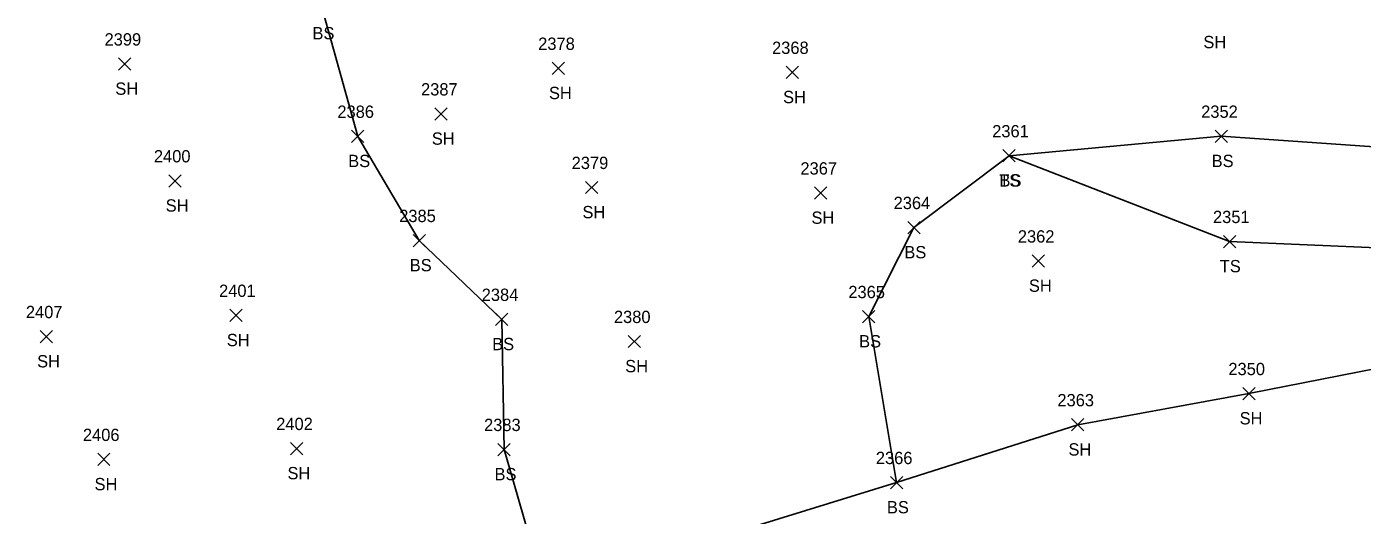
# Model space of a CAD drawing. Extents: x 1443590 to 1445966, y 578314 to 580556.
# Drawn here: x 1444550.7 to 1444767.8, y 578975.6 to 579055 of the extents above; entities that cross this region are included whole.
import ezdxf

# ---------------------------------------------------------------- set-up
doc = ezdxf.new("R2010")
doc.units = 0
for name, color, linetype in [('L_A', 7, 'Continuous'), ('L_I', 7, 'Continuous'), ('L_TIC', 7, 'Continuous'), ('LELB', 7, 'Continuous'), ('LSOGP', 7, 'Continuous')]:
    doc.layers.add(name, color=color, linetype=linetype)

msp = doc.modelspace()

# ---------------------------------------------------------------- linework, layer by layer
at = {"layer": 'L_TIC'}
for points in [[(1444565.63, 579047.93), (1444567.63, 579049.93)], [(1444567.63, 579047.93), (1444565.63, 579049.93)], [(1444636.1, 579047.23), (1444638.1, 579049.23)], [(1444638.1, 579047.23), (1444636.1, 579049.23)], [(1444674.16, 579046.57), (1444676.16, 579048.57)], [(1444676.16, 579046.57), (1444674.16, 579048.57)], [(1444617.06, 579039.82), (1444619.06, 579041.82)], [(1444619.06, 579039.82), (1444617.06, 579041.82)], [(1444603.52, 579036.18), (1444605.52, 579038.18)], [(1444605.52, 579036.18), (1444603.52, 579038.18)], [(1444743.86, 579036.19), (1444745.86, 579038.19)], [(1444745.86, 579036.19), (1444743.86, 579038.19)], [(1444709.37, 579033.02), (1444711.37, 579035.02)], [(1444711.37, 579033.02), (1444709.37, 579035.02)], [(1444709.37, 579033.02), (1444711.37, 579035.02)], [(1444711.37, 579033.02), (1444709.37, 579035.02)], [(1444573.8, 579028.95), (1444575.8, 579030.95)], [(1444575.8, 579028.95), (1444573.8, 579030.95)], [(1444641.55, 579027.87), (1444643.55, 579029.87)], [(1444643.55, 579027.87), (1444641.55, 579029.87)], [(1444678.77, 579026.97), (1444680.77, 579028.97)], [(1444680.77, 579026.97), (1444678.77, 579028.97)], [(1444693.91, 579021.36), (1444695.91, 579023.36)], [(1444695.91, 579021.36), (1444693.91, 579023.36)], [(1444613.51, 579019.25), (1444615.51, 579021.25)], [(1444615.51, 579019.25), (1444613.51, 579021.25)], [(1444745.21, 579019.09), (1444747.21, 579021.09)], [(1444747.21, 579019.09), (1444745.21, 579021.09)], [(1444714.11, 579015.92), (1444716.11, 579017.92)], [(1444716.11, 579015.92), (1444714.11, 579017.92)], [(1444583.74, 579007.09), (1444585.74, 579009.09)], [(1444585.74, 579007.09), (1444583.74, 579009.09)], [(1444626.92, 579006.44), (1444628.92, 579008.44)], [(1444628.92, 579006.44), (1444626.92, 579008.44)], [(1444686.56, 579006.89), (1444688.56, 579008.89)], [(1444688.56, 579006.89), (1444686.56, 579008.89)], [(1444552.91, 579003.64), (1444554.91, 579005.64)], [(1444554.91, 579003.64), (1444552.91, 579005.64)], [(1444648.49, 579002.85), (1444650.49, 579004.85)], [(1444650.49, 579002.85), (1444648.49, 579004.85)], [(1444748.36, 578994.38), (1444750.36, 578996.38)], [(1444750.36, 578994.38), (1444748.36, 578996.38)], [(1444720.54, 578989.32), (1444722.54, 578991.32)], [(1444722.54, 578989.32), (1444720.54, 578991.32)], [(1444593.6, 578985.46), (1444595.6, 578987.46)], [(1444595.6, 578985.46), (1444593.6, 578987.46)], [(1444627.3, 578985.3), (1444629.3, 578987.3)], [(1444629.3, 578985.3), (1444627.3, 578987.3)], [(1444562.24, 578983.68), (1444564.24, 578985.68)], [(1444564.24, 578983.68), (1444562.24, 578985.68)], [(1444691.08, 578979.93), (1444693.08, 578981.93)], [(1444693.08, 578979.93), (1444691.08, 578981.93)]]:
    msp.add_lwpolyline(points, dxfattribs=at)
at = {"layer": 'LELB'}
for points in [[(1444634.71, 578964.14), (1444628.3, 578986.3), (1444627.92, 579007.44), (1444614.51, 579020.25), (1444604.52, 579037.18), (1444598.71, 579057.94), (1444590.79, 579076.63), (1444589.4, 579093.21)], [(1444780.63, 579034.73), (1444744.86, 579037.19), (1444710.37, 579034.02), (1444694.91, 579022.36), (1444687.56, 579007.89), (1444692.08, 578980.93)], [(1444784.06, 579018.45), (1444746.21, 579020.09), (1444710.37, 579034.02)]]:
    msp.add_lwpolyline(points, dxfattribs=at)
at = {"layer": 'LSOGP'}
msp.add_lwpolyline([(1444658.23, 578970.47), (1444692.09, 578980.93), (1444721.54, 578990.32), (1444749.37, 578995.38), (1444787.96, 579002.98)], dxfattribs=at)

# ---------------------------------------------------------------- texts
at = {"layer": 'L_A'}
for s, p in [('BS', (1444597.15, 579052.94)), ('SH', (1444741.95, 579051.5)), ('SH', (1444565.11, 579043.93)), ('SH', (1444635.59, 579043.23)), ('SH', (1444673.64, 579042.57)), ('SH', (1444616.55, 579035.82)), ('BS', (1444602.96, 579032.18)), ('BS', (1444743.3, 579032.19)), ('TS', (1444708.78, 579029.02)), ('BS', (1444708.81, 579029.02)), ('SH', (1444573.29, 579024.95)), ('SH', (1444641.03, 579023.87)), ('SH', (1444678.26, 579022.97)), ('BS', (1444693.35, 579017.36)), ('BS', (1444612.96, 579015.25)), ('TS', (1444744.62, 579015.09)), ('SH', (1444713.6, 579011.92)), ('SH', (1444583.23, 579003.09)), ('BS', (1444626.36, 579002.44)), ('BS', (1444686, 579002.89)), ('SH', (1444552.4, 578999.64)), ('SH', (1444647.98, 578998.85)), ('SH', (1444747.85, 578990.38)), ('SH', (1444720.03, 578985.32)), ('SH', (1444593.09, 578981.46)), ('BS', (1444626.74, 578981.3)), ('SH', (1444561.73, 578979.68)), ('BS', (1444690.52, 578975.93))]:
    msp.add_text(s, height=2, dxfattribs=at).set_placement(p)
at = {"layer": 'L_I'}
for s, p in [('2399', (1444563.36, 579051.93)), ('2378', (1444633.84, 579051.23)), ('2368', (1444671.85, 579050.57)), ('2387', (1444614.8, 579043.82)), ('2386', (1444601.2, 579040.18)), ('2352', (1444741.6, 579040.19)), ('2361', (1444707.63, 579037.02)), ('2361', (1444707.63, 579037.02)), ('2400', (1444571.38, 579032.95)), ('2379', (1444639.28, 579031.87)), ('2367', (1444676.46, 579030.97)), ('2364', (1444691.61, 579025.36)), ('2385', (1444611.25, 579023.25)), ('2351', (1444743.52, 579023.09)), ('2362', (1444711.8, 579019.92)), ('2401', (1444581.97, 579011.09)), ('2384', (1444624.66, 579010.44)), ('2365', (1444684.25, 579010.89)), ('2407', (1444550.57, 579007.64)), ('2380', (1444646.15, 579006.85)), ('2350', (1444746.02, 578998.38)), ('2363', (1444718.23, 578993.32)), ('2402', (1444591.26, 578989.46)), ('2383', (1444625.04, 578989.3)), ('2406', (1444559.84, 578987.68)), ('2366', (1444688.72, 578983.93))]:
    msp.add_text(s, height=2, dxfattribs=at).set_placement(p)

doc.saveas('drawing.dxf')
